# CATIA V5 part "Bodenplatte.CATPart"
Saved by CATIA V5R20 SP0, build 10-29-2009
Part number: Bodenplatte
Bounding box of the stored display mesh (mm): x -750 to 750, y -500 to 500, z 0 to 18
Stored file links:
  C:\Users\Andi\Desktop\Offene Projekte\Plasmacutter\Rahmen\Bodenplatte.CATPart
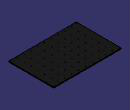
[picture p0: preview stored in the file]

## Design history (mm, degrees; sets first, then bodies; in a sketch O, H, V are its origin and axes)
Body1 (main body)
  Sketch1 on xy-plane, origin (0, 0, 0), H (1, 0, 0), V (0, 1, 0)
    line L1 (750, 500) -> (750, -500)
    line L2 (750, -500) -> (-750, -500)
    line L3 (-750, -500) -> (-750, 500)
    line L4 (-750, 500) -> (750, 500)
    distance L2 L4 = 1000
    distance L1 L3 = 1500
    vertical: L1 V, L3 V
    horizontal: L2 H, L4 H
    equidistance: L1 L3 O, L2 L4 O
  Pad1: profile Sketch1, direction (0, 0, 1), length 18
  Sketch2 on end face of Pad1, origin (-696.8741, 501.7494, 18), H (1, 0, 0), V (0, 1, 0)
    point P1 (-33.1259, -21.7494)
    reference intersected line E1 (-53.1259, -1.7494) -> (1446.8741, -1.7494) from face of Pad1 from Sketch1.L4
    reference intersected line E2 (-53.1259, -1041.7494) -> (-53.1259, 38.2506) from face of Pad1 from Sketch1.L3
    distance E1 P1 = 20
    distance E2 P1 = 20
  Hole1: placed by Sketch2, at (-730, 480, 18) direction (0, 0, -1), diameter 8, through (limit type 6)
  RectPattern1: of Hole1, direction 1 instances 3, spacing 730, along end face of Pad1, direction 2 instances 2, spacing 960, along end face of Pad1 reversed
  Sketch3 on end face of Pad1, origin (652.2668, -451.8369, 18), H (1, 0, 0), V (0, 1, 0)
    point P1 (-52.2668, 1.8369)
    reference intersected line E1 through (0, 451.8369) direction (-1, 0) from zx-plane
    reference intersected line E2 through (-652.2668, 0) direction (0, 1) from yz-plane
    distance E1 P1 = 450
    distance E2 P1 = 600
  Hole2: placed by Sketch3, at (600, -450, 18) direction (0, 0, -1), diameter 11, through (limit type 6)
  RectPattern2: of Hole2, direction 1 instances 9, spacing 150, along end face of Pad1 reversed, direction 2 instances 7, spacing 150, along end face of Pad1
